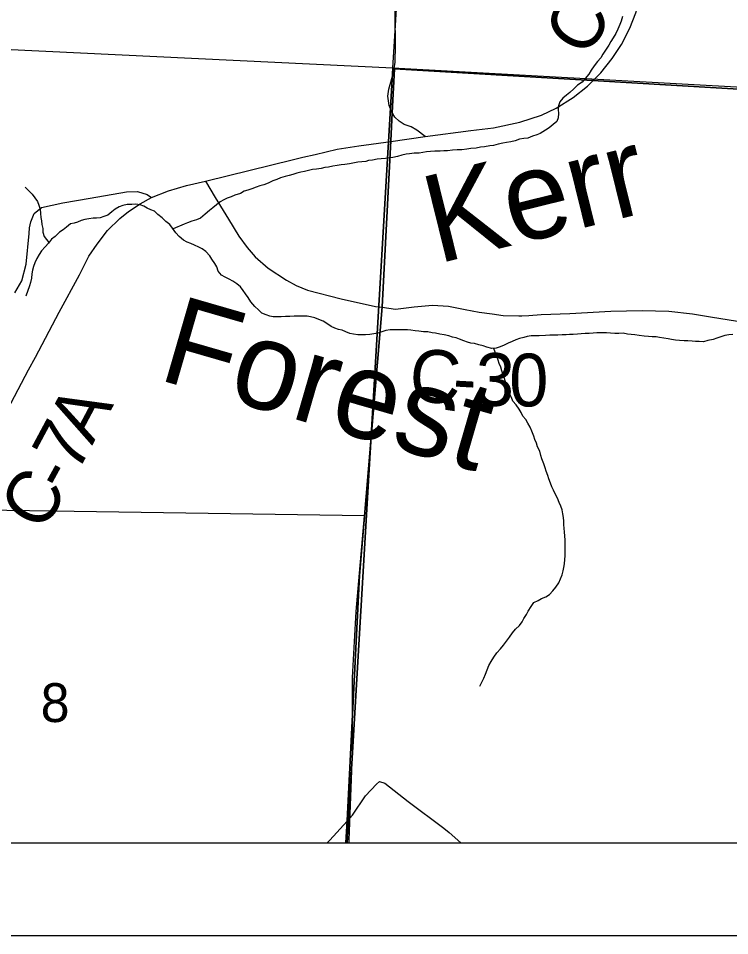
# Model space of a CAD drawing. Extents: x -20.2 to 34, y 0 to 22.
# Drawn here: x 6.324 to 7.09, y 14 to 14.988 of the extents above; entities that cross this region are included whole.
import ezdxf

# ---------------------------------------------------------------- set-up
doc = ezdxf.new("R2010")
doc.units = 0
for name, color, linetype in [('Default', 7, 'Continuous'), ('GM_X_County_Road', 7, 'Continuous'), ('GM_X_County_Road_Text', 7, 'Continuous'), ('GM_X_Minor_River', 7, 'Continuous'), ('GM_X_Minor_River_Text', 7, 'Continuous'), ('GM_X_Section', 7, 'Continuous'), ('GM_X_Section_Text', 7, 'Continuous'), ('GM_X_State_Route', 7, 'Continuous'), ('GM_X_Township_Road', 7, 'Continuous'), ('SH_Cut_Line', 7, 'Continuous'), ('SH_Data', 7, 'Continuous')]:
    doc.layers.add(name, color=color, linetype=linetype)

msp = doc.modelspace()

# ---------------------------------------------------------------- linework, layer by layer
at = {"layer": 'Default'}
for points in [[(5.77351, 14.1), (6.67705, 14.1), (6.67825, 14.12402), (6.69148, 14.38791), (6.71588, 14.67753), (6.72527, 14.85632), (6.72684, 14.88665), (6.7293, 14.93376), (6.94241, 14.92118), (7.46907, 14.89011), (7.80177, 14.87554), (7.8434, 15.55866)], [(5.76472, 14.1), (6.68038, 14.1), (6.68049, 14.10288), (6.68422, 14.19619), (6.68422, 14.27831), (6.68795, 14.34923), (6.69691, 14.4523), (5.95079, 14.46346)]]:
    msp.add_lwpolyline(points, dxfattribs=at)
for points in [[(6.028, 14.1), (6.67837, 14.1), (6.72741, 14.93458), (6.13668, 14.9631), (5.65328, 14.98393), (5.63839, 14.73635), (5.61622, 14.35816), (5.60053, 14.12693), (5.62781, 14.12705), (5.64978, 14.12792), (5.67326, 14.13031), (5.68614, 14.13075), (5.71607, 14.13165), (5.75132, 14.12955), (5.78466, 14.12782), (5.81195, 14.1272), (5.82256, 14.12611), (5.84151, 14.12582), (5.8745, 14.1203), (5.90219, 14.11513), (5.93631, 14.11151), (5.95792, 14.1082), (5.98331, 14.10719), (6.01477, 14.10317)], [(6.67705, 14.1), (8.9, 14.1), (8.9, 14.81759), (8.83066, 14.81994), (8.80435, 14.82053), (8.75184, 14.82421), (7.80177, 14.87554), (7.46907, 14.89011), (6.94241, 14.92118), (6.7293, 14.93376), (6.72684, 14.88665), (6.72527, 14.85632), (6.71588, 14.67753), (6.69148, 14.38791), (6.67825, 14.12402)], [(6.67837, 14.1), (7.75338, 14.1), (7.79854, 14.87534), (6.72741, 14.93458)]]:
    msp.add_lwpolyline(points, close=True, dxfattribs=at)
at = {"layer": 'GM_X_County_Road'}
for points in [[(6.52573, 14.81303), (6.53629, 14.79522), (6.55064, 14.77197), (6.56176, 14.75378), (6.57085, 14.74145), (6.57914, 14.73134), (6.59323, 14.719), (6.6131, 14.70628), (6.62331, 14.70066), (6.63574, 14.69556), (6.67193, 14.68606), (6.70872, 14.67797), (6.71609, 14.67701), (6.73035, 14.67514), (6.75037, 14.67757), (6.77018, 14.67918), (6.78756, 14.67818), (6.80555, 14.67474), (6.82051, 14.67191), (6.83446, 14.66989), (6.84618, 14.66827), (6.86337, 14.66786), (6.86629, 14.66792)], [(6.86629, 14.66792), (6.87408, 14.66807), (6.88722, 14.66908), (6.91795, 14.67049), (6.96242, 14.67292), (6.99598, 14.67352), (7.02489, 14.67271), (7.05015, 14.66989), (7.0717, 14.66635), (7.15489, 14.65292)]]:
    msp.add_lwpolyline(points, dxfattribs=at)
at = {"layer": 'GM_X_Minor_River'}
for points in [[(6.97498, 14.9903), (6.97349, 14.98536), (6.972, 14.98154), (6.96976, 14.97659), (6.96752, 14.97202), (6.96489, 14.96744), (6.96227, 14.96324), (6.96002, 14.95943), (6.95664, 14.95408), (6.95363, 14.94988), (6.95138, 14.94569), (6.94799, 14.94186), (6.94423, 14.93728), (6.94123, 14.93232), (6.9386, 14.92812), (6.93446, 14.92353), (6.93145, 14.91971), (6.92654, 14.91625), (6.92239, 14.91243), (6.91824, 14.9086), (6.91447, 14.90553), (6.9107, 14.90246), (6.90731, 14.89826), (6.90582, 14.89407), (6.90547, 14.89027), (6.90588, 14.88571), (6.90554, 14.88115), (6.90405, 14.87734), (6.90028, 14.8739), (6.89574, 14.87045), (6.89197, 14.86776), (6.8863, 14.8643), (6.88251, 14.86275), (6.87797, 14.8612), (6.87304, 14.85926), (6.86849, 14.85885), (6.86394, 14.85806), (6.85939, 14.85651), (6.85447, 14.85533), (6.84992, 14.85454), (6.84613, 14.85375), (6.84082, 14.85258), (6.83589, 14.8514), (6.8321, 14.85099), (6.82641, 14.84981), (6.82185, 14.8494), (6.8173, 14.84861), (6.81161, 14.84819)], [(6.81161, 14.84819), (6.80706, 14.8474), (6.80175, 14.8466), (6.79681, 14.84656), (6.79188, 14.84615), (6.78657, 14.84573), (6.78239, 14.8457), (6.7786, 14.84529), (6.7729, 14.84525), (6.76797, 14.84484), (6.76379, 14.84443), (6.76, 14.84364), (6.75583, 14.84323), (6.75051, 14.84319), (6.74558, 14.84239), (6.74179, 14.84199), (6.73724, 14.84082), (6.73269, 14.83964), (6.72739, 14.83847), (6.72359, 14.83806), (6.7198, 14.83727), (6.71487, 14.83686), (6.71069, 14.83645), (6.70576, 14.83565), (6.70121, 14.83524), (6.69837, 14.83415), (6.68983, 14.83326), (6.68452, 14.83246), (6.68073, 14.83167), (6.6758, 14.83088), (6.67201, 14.83047), (6.66746, 14.82968), (6.6629, 14.82889), (6.65835, 14.8281), (6.65418, 14.82768), (6.65039, 14.82652), (6.64546, 14.82572), (6.64091, 14.82531), (6.63673, 14.82452), (6.63257, 14.82335), (6.62839, 14.82256), (6.62423, 14.82139), (6.61968, 14.82022), (6.61589, 14.81905), (6.61172, 14.81788), (6.60642, 14.81632), (6.60263, 14.81478), (6.59847, 14.81323), (6.59317, 14.81091), (6.58863, 14.80898), (6.58446, 14.80781), (6.58029, 14.80626), (6.57575, 14.80471), (6.57158, 14.80316), (6.56741, 14.80199), (6.56363, 14.79968), (6.55757, 14.79774), (6.55341, 14.79619), (6.54924, 14.79464), (6.54546, 14.79271), (6.54167, 14.79079), (6.53752, 14.78734), (6.53375, 14.78427), (6.52997, 14.7812), (6.52545, 14.77737), (6.52054, 14.77316), (6.516, 14.77122), (6.51107, 14.76967), (6.50653, 14.76812), (6.50274, 14.76657), (6.49085, 14.76144)], [(6.33165, 14.80638), (6.33922, 14.79883), (6.34191, 14.79505), (6.34498, 14.79089), (6.34653, 14.78711), (6.3477, 14.78256), (6.34811, 14.778), (6.34852, 14.77382), (6.34931, 14.77003), (6.34972, 14.76623), (6.35051, 14.76206), (6.35054, 14.75788), (6.35209, 14.75333), (6.35726, 14.74684)], [(6.75156, 14.65172), (6.74699, 14.65244), (6.7432, 14.6528), (6.7394, 14.65277), (6.73408, 14.65273), (6.72915, 14.6527), (6.72459, 14.65266), (6.72004, 14.65187), (6.71587, 14.6507), (6.71133, 14.64915), (6.70715, 14.64836), (6.7026, 14.64757), (6.69805, 14.64715), (6.69349, 14.6475), (6.68969, 14.64747), (6.68513, 14.6482), (6.68133, 14.64893), (6.67676, 14.65042), (6.67295, 14.65229), (6.66915, 14.65303), (6.66496, 14.65452), (6.66115, 14.65639), (6.65657, 14.65939), (6.65237, 14.66202), (6.6478, 14.66389), (6.64361, 14.66576), (6.63905, 14.66687), (6.63524, 14.6676), (6.63069, 14.66757), (6.62613, 14.66754), (6.6212, 14.6675), (6.61664, 14.66709), (6.61208, 14.66705), (6.60715, 14.66664), (6.60335, 14.66661), (6.5988, 14.66658), (6.59499, 14.66731), (6.59119, 14.6688), (6.58662, 14.67067), (6.58279, 14.67444), (6.57897, 14.67784), (6.57475, 14.68274), (6.57168, 14.68766), (6.56899, 14.69144), (6.56631, 14.69522), (6.56362, 14.699), (6.55942, 14.70239), (6.55522, 14.70502), (6.55141, 14.70727), (6.54684, 14.70952), (6.54302, 14.71177), (6.53957, 14.71593), (6.53802, 14.72047), (6.53571, 14.72426), (6.53264, 14.72879), (6.53034, 14.73258), (6.52613, 14.73711), (6.52231, 14.74012), (6.5185, 14.74161), (6.51392, 14.74386), (6.51011, 14.74573), (6.50592, 14.74722), (6.50211, 14.74947), (6.49753, 14.75324), (6.4937, 14.75739), (6.49024, 14.7623), (6.48756, 14.76608), (6.48298, 14.76947), (6.47915, 14.77324), (6.47457, 14.77701), (6.47074, 14.7804), (6.46694, 14.78189), (6.46313, 14.78376), (6.45931, 14.78602), (6.4555, 14.78751), (6.45094, 14.78824), (6.44639, 14.78782), (6.44145, 14.78779), (6.4369, 14.78662), (6.43274, 14.78507), (6.42858, 14.78276), (6.42481, 14.77969), (6.42065, 14.77624), (6.41649, 14.77469), (6.41232, 14.77352), (6.40853, 14.77311), (6.40473, 14.77309), (6.40018, 14.7723), (6.39601, 14.77151), (6.39184, 14.77034), (6.38805, 14.76879), (6.38426, 14.76762), (6.38047, 14.76683), (6.37632, 14.76339), (6.37255, 14.76032), (6.36877, 14.75801), (6.36386, 14.75342), (6.36009, 14.75035), (6.35671, 14.74615), (6.35332, 14.74232), (6.34917, 14.73774)], [(6.34917, 14.73774), (6.34654, 14.73392), (6.3443, 14.72972), (6.34205, 14.72477), (6.34056, 14.72096), (6.33945, 14.71715), (6.33872, 14.71296), (6.33838, 14.7084), (6.33727, 14.70384), (6.33616, 14.70003), (6.3323, 14.68898)], [(7.09371, 14.64771), (7.08916, 14.6473), (7.08499, 14.64651), (7.08082, 14.64534), (7.07628, 14.64378), (7.07249, 14.64224), (7.06681, 14.64106), (7.06188, 14.63988), (7.05732, 14.64023), (7.05352, 14.6402), (7.04972, 14.64055), (7.04516, 14.6409), (7.04136, 14.64087), (7.03605, 14.64122), (7.03187, 14.64157), (7.02768, 14.6423), (7.02388, 14.64303), (7.01932, 14.64375), (7.01476, 14.64448), (7.01096, 14.64521), (7.00678, 14.64518), (7.00298, 14.64554), (6.99804, 14.64588), (6.99272, 14.64661), (6.98815, 14.64733), (6.98435, 14.64768), (6.98017, 14.64803), (6.97561, 14.64914), (6.97106, 14.64873), (6.9665, 14.6487), (6.96194, 14.64904), (6.95776, 14.64939), (6.95245, 14.64936), (6.94713, 14.64932), (6.94333, 14.64929), (6.93878, 14.64888), (6.9346, 14.64885), (6.93043, 14.64844), (6.92626, 14.64803), (6.9217, 14.64762), (6.91791, 14.64759), (6.91411, 14.64718), (6.90993, 14.64715), (6.90538, 14.64712), (6.90158, 14.64709), (6.89664, 14.64706), (6.89209, 14.64664), (6.88526, 14.64621), (6.88108, 14.64618), (6.87653, 14.64615), (6.87235, 14.64536), (6.86857, 14.64458), (6.86402, 14.6434), (6.85985, 14.64186), (6.85607, 14.64031), (6.8519, 14.63838), (6.84736, 14.63607), (6.8432, 14.63452), (6.83865, 14.63296), (6.8341, 14.63255), (6.82877, 14.63403), (6.82496, 14.63553), (6.82002, 14.63663), (6.81545, 14.63812), (6.81165, 14.63847), (6.80785, 14.63958), (6.80404, 14.6407), (6.79947, 14.64256), (6.79566, 14.64405), (6.79186, 14.64479), (6.78767, 14.64628), (6.78273, 14.64738), (6.77816, 14.64811), (6.7736, 14.64921), (6.7698, 14.64957), (6.76523, 14.65068), (6.76068, 14.65064), (6.75536, 14.65136), (6.75156, 14.65172)], [(6.82124, 14.26886), (6.82349, 14.27305), (6.82535, 14.27725), (6.82722, 14.28182), (6.82908, 14.28639), (6.83094, 14.29097), (6.83357, 14.29554), (6.83619, 14.30012), (6.83958, 14.30471), (6.84334, 14.30891), (6.84673, 14.31311), (6.85011, 14.31732), (6.85312, 14.32152), (6.8565, 14.3261), (6.85951, 14.3303), (6.86404, 14.33414), (6.86667, 14.33795), (6.86854, 14.34177), (6.87155, 14.34597), (6.87342, 14.34978), (6.87642, 14.35474), (6.87942, 14.35894), (6.88396, 14.36125), (6.88775, 14.36318), (6.89229, 14.36511), (6.89607, 14.36742), (6.89983, 14.37163), (6.90322, 14.37545), (6.90623, 14.38003), (6.90809, 14.38461), (6.90996, 14.3888), (6.91107, 14.39298), (6.9118, 14.39679), (6.91253, 14.40059), (6.91287, 14.40515), (6.91322, 14.40934), (6.91319, 14.4139), (6.91316, 14.41769), (6.91313, 14.42225), (6.9131, 14.42605), (6.91268, 14.43061), (6.91228, 14.43479), (6.91186, 14.43896), (6.91184, 14.44276), (6.91181, 14.44656), (6.9114, 14.45036), (6.91061, 14.45453), (6.90982, 14.45871), (6.90827, 14.46287), (6.90672, 14.46666), (6.90479, 14.47121), (6.90286, 14.47537), (6.90055, 14.47991), (6.89862, 14.4837), (6.89745, 14.48749), (6.89552, 14.49204), (6.89435, 14.49583), (6.8928, 14.50037), (6.89163, 14.50417), (6.89008, 14.50833), (6.88814, 14.51364), (6.88698, 14.51743), (6.8858, 14.52198), (6.88349, 14.52652), (6.88232, 14.53069), (6.88039, 14.53448), (6.87923, 14.53827), (6.87729, 14.54358), (6.87536, 14.54774), (6.87305, 14.55229), (6.87074, 14.55607), (6.86767, 14.55985), (6.86575, 14.56363), (6.86344, 14.56741), (6.86037, 14.57195), (6.85692, 14.57572), (6.85537, 14.57989), (6.85307, 14.58368), (6.85114, 14.58822), (6.84997, 14.59201), (6.8488, 14.59656), (6.84763, 14.60035), (6.84608, 14.6049), (6.84491, 14.60869), (6.84374, 14.61248), (6.84219, 14.61627), (6.84103, 14.62006), (6.83624, 14.63274)]]:
    msp.add_lwpolyline(points, dxfattribs=at)
at = {"layer": 'GM_X_Section'}
msp.add_lwpolyline([(6.79044, 15.94473), (7.86237, 15.87982), (7.79854, 14.87534), (6.72741, 14.93458), (6.77473, 15.69297)], close=True, dxfattribs=at)
at = {"layer": 'GM_X_State_Route'}
for points in [[(6.76226, 14.86085), (6.81156, 14.86754), (6.83594, 14.87041), (6.86415, 14.87629), (6.88758, 14.8841), (6.90338, 14.89172), (6.92172, 14.90317), (6.93716, 14.91534), (6.94262, 14.92066), (6.95168, 14.9295), (6.96386, 14.94494), (6.97384, 14.96019), (6.98256, 14.97763), (6.9891, 14.99434), (6.99364, 15.00887)], [(6.29507, 14.53398), (6.30113, 14.54538), (6.33527, 14.60967), (6.34272, 14.62329), (6.36814, 14.6716), (6.39012, 14.71192), (6.40029, 14.73208), (6.40919, 14.74515), (6.42045, 14.75987), (6.43353, 14.77258), (6.44298, 14.78021), (6.45532, 14.78838), (6.46758, 14.79535), (6.48584, 14.80237), (6.50554, 14.80813), (6.52573, 14.81303), (6.62041, 14.83615), (6.63059, 14.83869), (6.64403, 14.8416), (6.66764, 14.84723), (6.69078, 14.8509), (6.72548, 14.8558), (6.76226, 14.86085)]]:
    msp.add_lwpolyline(points, dxfattribs=at)
at = {"layer": 'GM_X_Township_Road'}
for points in [[(6.76226, 14.86085), (6.75355, 14.86767), (6.74717, 14.87142), (6.73967, 14.87405), (6.73422, 14.87743), (6.72953, 14.88174), (6.72705, 14.88612), (6.72634, 14.88737), (6.72353, 14.89432), (6.72203, 14.90464), (6.72316, 14.91215), (6.72785, 14.92866), (6.72991, 14.94067), (6.73028, 14.95925), (6.7301, 14.99171), (6.72973, 15.01273), (6.72945, 15.02829)], [(6.32038, 14.69267), (6.32801, 14.70538), (6.33273, 14.72336), (6.33582, 14.7566), (6.33618, 14.76278), (6.33763, 14.76913), (6.34145, 14.77803), (6.34925, 14.78439), (6.37214, 14.78966), (6.40156, 14.79474), (6.44079, 14.80128), (6.4526, 14.80182), (6.46295, 14.79855), (6.46758, 14.79535)], [(6.65695, 14.1), (6.6598, 14.10279), (6.67846, 14.12349), (6.68419, 14.12984), (6.69817, 14.15074), (6.7099, 14.16331), (6.71322, 14.16619), (6.71899, 14.1642), (6.74404, 14.14469), (6.7826, 14.11565), (6.78836, 14.11122), (6.80067, 14.1)]]:
    msp.add_lwpolyline(points, dxfattribs=at)
at = {"layer": 'SH_Cut_Line'}
msp.add_lwpolyline([(5.77351, 14.1), (8.9, 14.1), (8.9, 20.9), (2.1, 20.9), (2.1, 14.1), (5.39535, 14.1), (5.72679, 14.10759)], close=True, dxfattribs=at)
at = {"layer": 'SH_Data'}
for p, q in [((2.1, 14.1), (8.9, 14.1)), ((2, 14), (9, 14))]:
    msp.add_line(p, q, dxfattribs=at)

# ---------------------------------------------------------------- texts
at = {"layer": 'GM_X_County_Road_Text'}
for s, rotation, p in [('C', 57.24741, (6.93504, 14.94414)), ('C', 356.71972, (6.74433, 14.57571)), ('3', 357.54381, (6.81511, 14.57174)), ('0', 0.11659, (6.85286, 14.57018)), ('-', 356.90692, (6.79112, 14.57303)), ('A', 62.03126, (6.40371, 14.52767)), ('7', 61.85026, (6.38711, 14.49664)), ('C', 58.56969, (6.34983, 14.43326)), ('-', 61.38139, (6.37569, 14.47571))]:
    msp.add_text(s, height=0.05682, rotation=rotation, dxfattribs=at).set_placement(p)
at = {"layer": 'GM_X_Minor_River_Text'}
for s, height, rotation, p in [('Kerr', 0.094698, 13.8655, (6.77553, 14.72369)), ('Forest', 0.094699, 343.86316, (6.47306, 14.59959))]:
    msp.add_text(s, height=height, rotation=rotation, dxfattribs=at).set_placement(p)
at = {"layer": 'GM_X_Section_Text'}
msp.add_text('8', height=0.04186, rotation=0.00001, dxfattribs=at).set_placement((6.34833, 14.23016))

doc.saveas('drawing.dxf')
